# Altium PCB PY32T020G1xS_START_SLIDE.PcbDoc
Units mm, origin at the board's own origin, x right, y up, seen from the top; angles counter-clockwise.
Board outline 105.31 x 81.08 mm, 2 copper layers (Top Layer, Bottom Layer); 86 components, 86 nets, 275 pads, 131 vias.
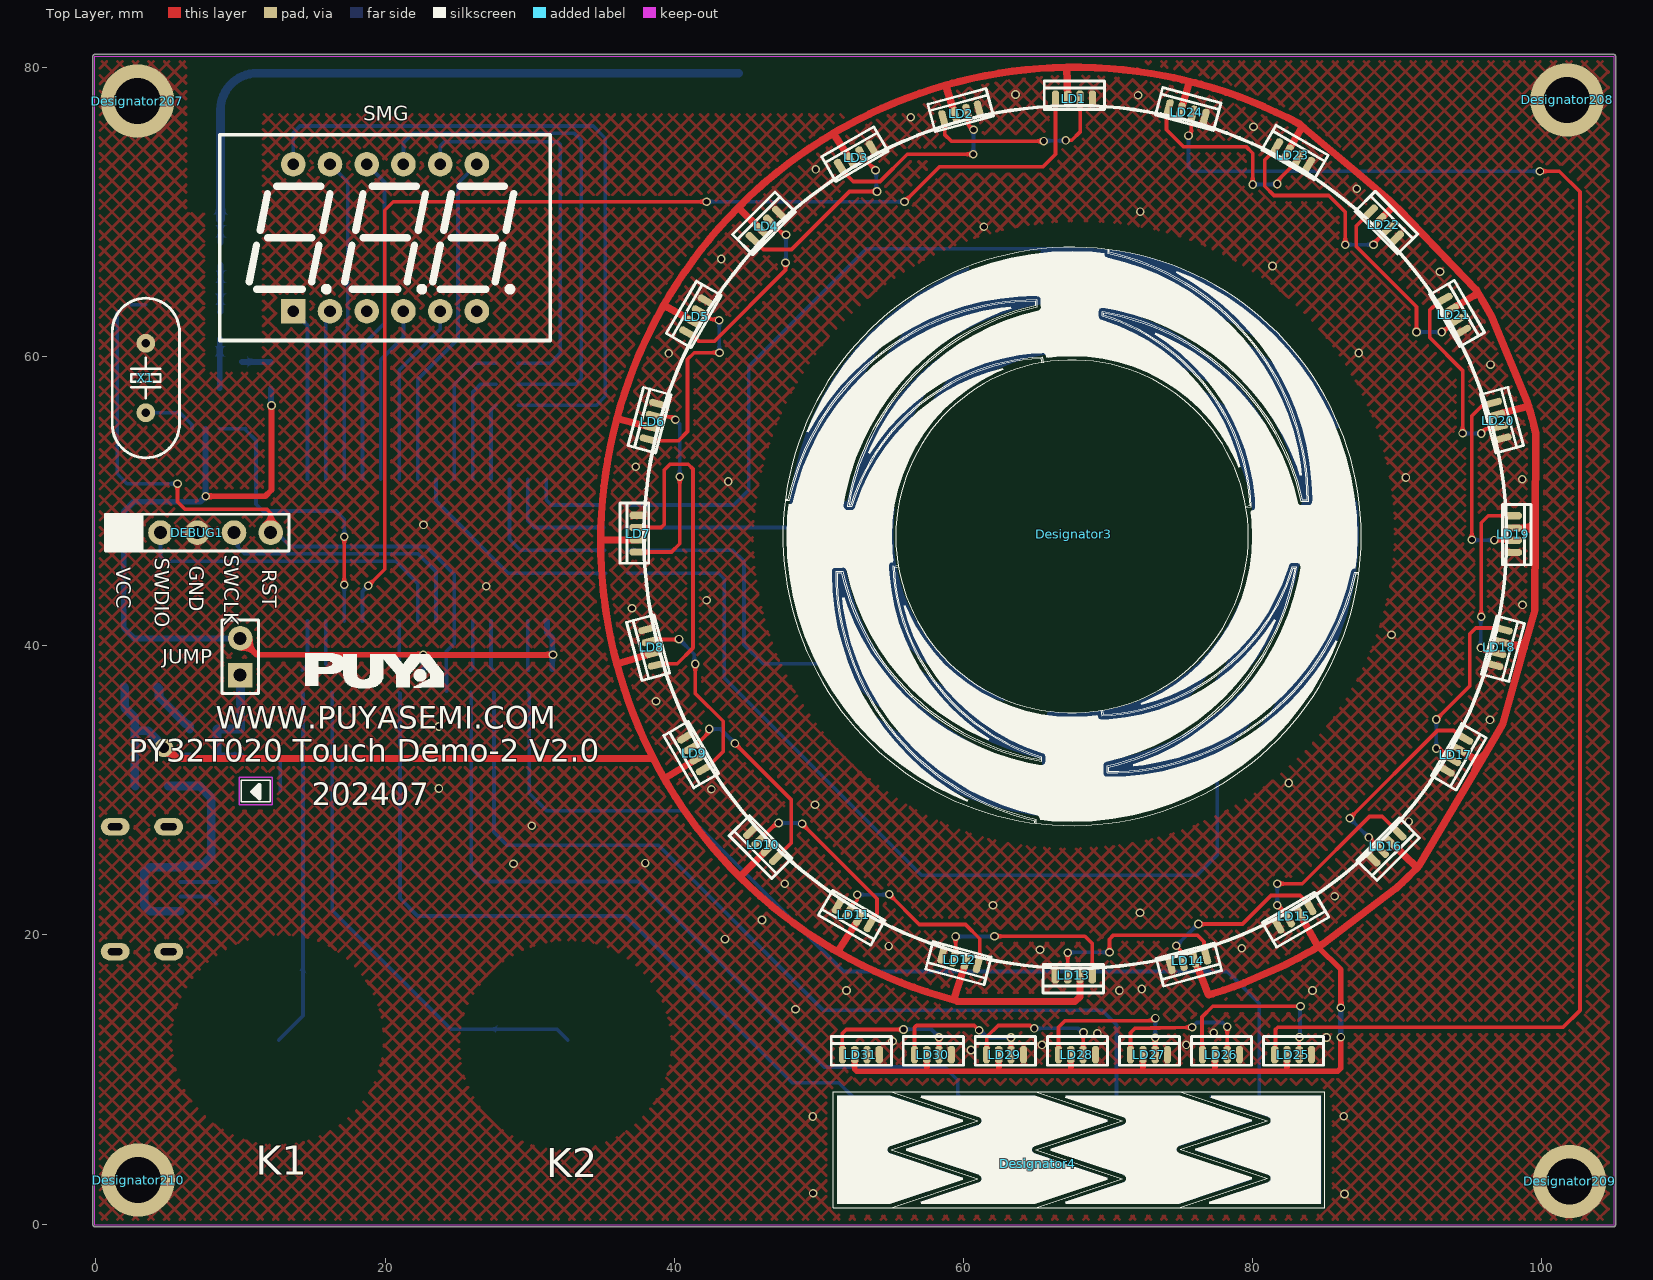
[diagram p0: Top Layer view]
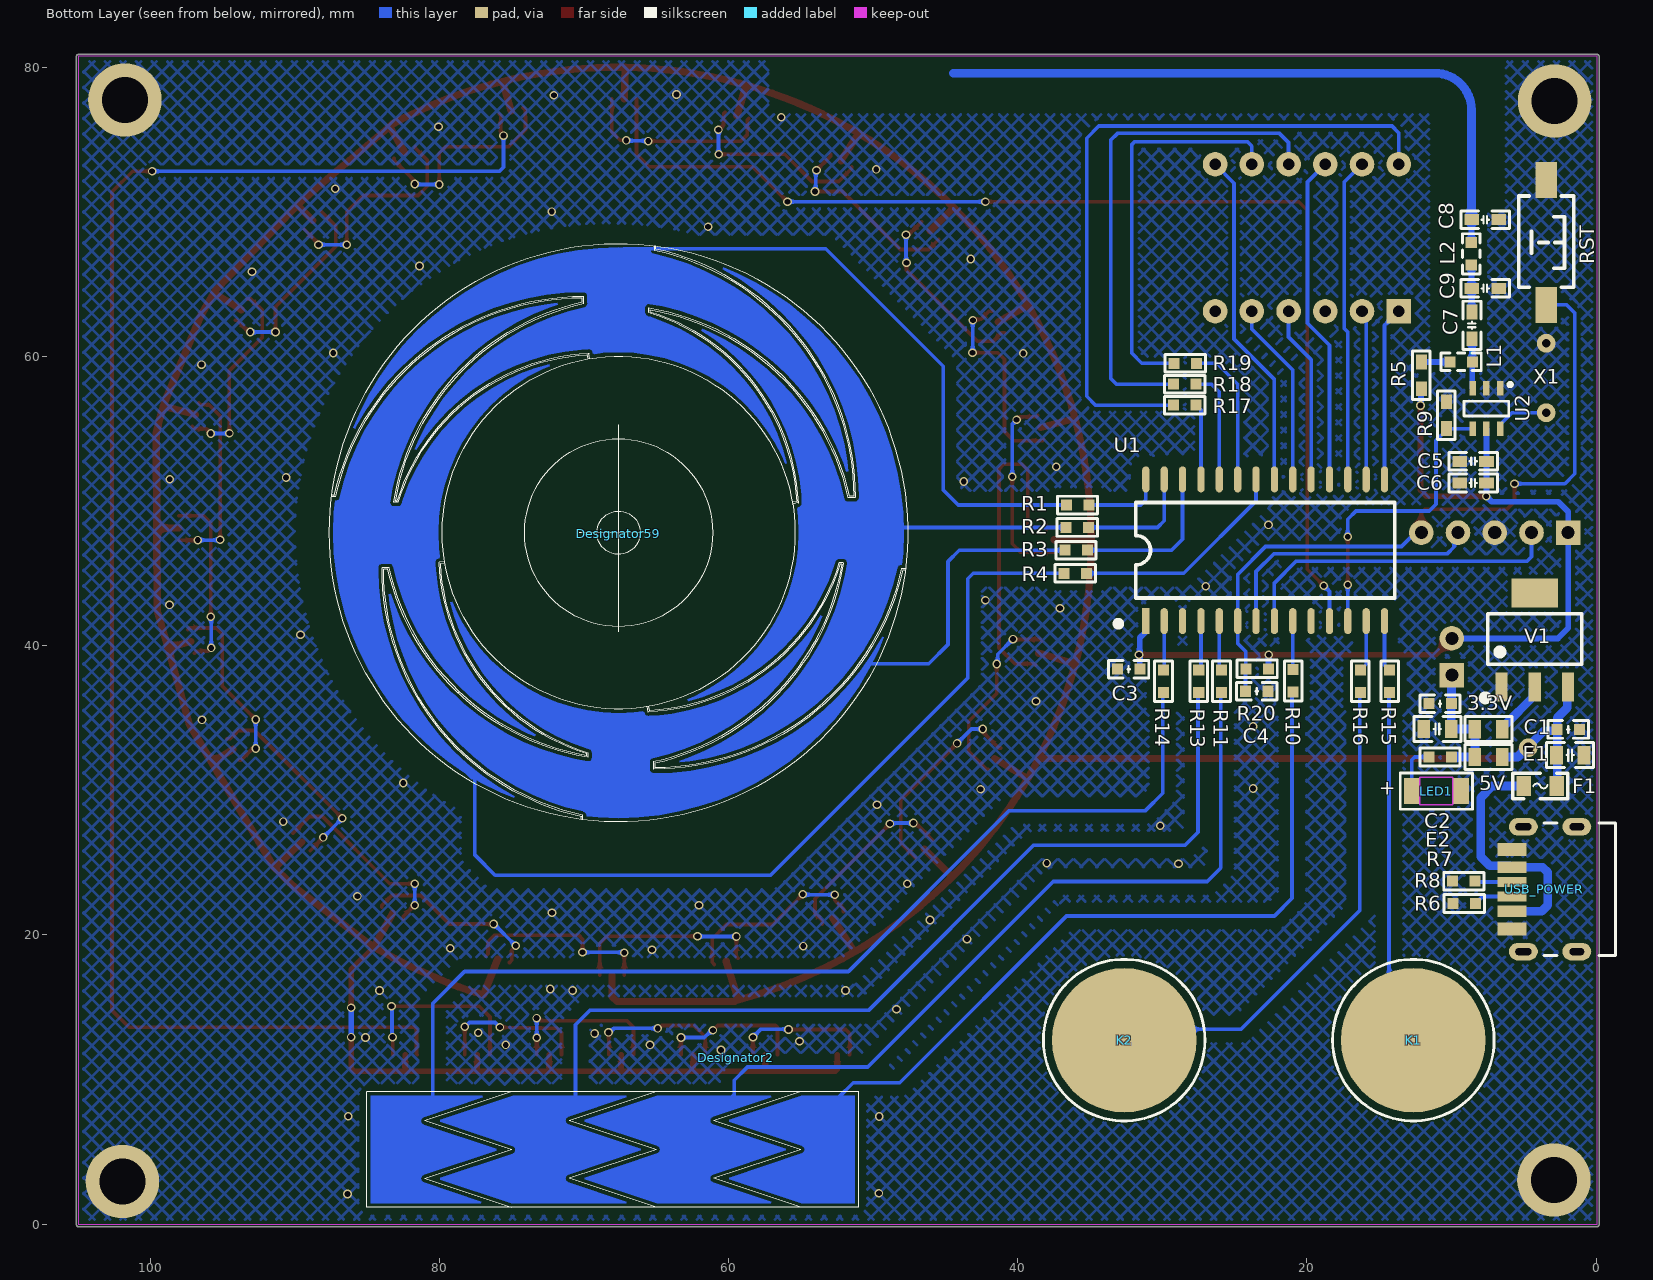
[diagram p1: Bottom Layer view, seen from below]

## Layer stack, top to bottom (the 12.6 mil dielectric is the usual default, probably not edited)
Top Solder: solder mask 0.0102, Solder Resist, Dk 3.5
Top Layer: signal copper 0.0356
Dielectric 1: dielectric 0.32, FR-4, Dk 4.8
Bottom Layer: signal copper 0.0356
Bottom Solder: solder mask 0.0102, Solder Resist, Dk 3.5

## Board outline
-0.076,-0.178 cw(c-0.076,-0.051) -0.204,-0.051 -0.204,80.772 cw(c-0.076,80.772) -0.076,80.899 104.978,80.899 cw(c104.978,80.772) 105.106,80.772 105.106,-0.051 cw(c104.978,-0.051) 104.978,-0.178

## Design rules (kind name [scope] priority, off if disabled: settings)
Clearance TK [InNet('TK1')] p1: gap=0.768 ignorepadtopadclearanceinfootprint=FALSE
Clearance NetR_10 [InNet('NetR16_2')] p2: gap=0.768 ignorepadtopadclearanceinfootprint=FALSE
Clearance NetR_9 [InNet('NetR15_2')] p3: gap=0.768 ignorepadtopadclearanceinfootprint=FALSE
Clearance NetR_8 [InNet('NetR14_2')] p4: gap=0.768 ignorepadtopadclearanceinfootprint=FALSE
Clearance NetR_7 [InNet('NetR13_2')] p5: gap=0.768 ignorepadtopadclearanceinfootprint=FALSE
Clearance NetR_6 [InNet('NetR11_2')] p6: gap=0.768 ignorepadtopadclearanceinfootprint=FALSE
Clearance NetR_5 [InNet('NetR10_2')] p7: gap=0.768 ignorepadtopadclearanceinfootprint=FALSE
Clearance NetR_4 [InNet('NetR4_2')] p8: gap=0.768 ignorepadtopadclearanceinfootprint=FALSE
Clearance NetR_3 [InNet('NetR3_2')] p9: gap=0.768 ignorepadtopadclearanceinfootprint=FALSE
Clearance NetR_2 [InNet('NetR2_2')] p10: gap=0.768 ignorepadtopadclearanceinfootprint=FALSE
Clearance NetR_1 [InNet('NetR1_2')] p11: gap=0.768 ignorepadtopadclearanceinfootprint=FALSE
Clearance TK_10 [InNet('TK10')] p12: gap=0.768 ignorepadtopadclearanceinfootprint=FALSE
Clearance TK_9 [InNet('TK9')] p13: gap=0.768 ignorepadtopadclearanceinfootprint=FALSE
Clearance TK_8 [InNet('TK8')] p14: gap=0.768 ignorepadtopadclearanceinfootprint=FALSE
Clearance TK_7 [InNet('TK7')] p15: gap=0.768 ignorepadtopadclearanceinfootprint=FALSE
Clearance TK_6 [InNet('TK6')] p16: gap=0.768 ignorepadtopadclearanceinfootprint=FALSE
Clearance TK_5 [InNet('TK5')] p17: gap=0.768 ignorepadtopadclearanceinfootprint=FALSE
Clearance TK_4 [InNet('TK4')] p18: gap=0.768 ignorepadtopadclearanceinfootprint=FALSE
Clearance TK_3 [InNet('TK3')] p19: gap=0.768 ignorepadtopadclearanceinfootprint=FALSE
Clearance TK_2 [InNet('TK2')] p20: gap=0.768 ignorepadtopadclearanceinfootprint=FALSE
Clearance TK_1 [InNet('TK1')] p21: gap=0.768 ignorepadtopadclearanceinfootprint=FALSE
Clearance [All] p22: gap=0.254 ignorepadtopadclearanceinfootprint=FALSE except(0: Arc-Hole Track-Hole SMDPad-Hole THPad-Hole Via-Hole Fill-Hole Poly-Hole Region-Hole Text-Hole)
PlaneConnect PlaneConnect_1 [InNet('GND')] p1: planeconnectstyle=Direct reliefexpansion=0.508 reliefentries=4 reliefconductorwidth=0.254 reliefairgap=0.254
PlaneConnect [All] p2: planeconnectstyle=Relief reliefexpansion=0.508 reliefentries=4 reliefconductorwidth=0.254 reliefairgap=0.254
PolygonConnect PolygonConnect_1 [InNet('GND')] p1: connectstyle=Direct reliefconductorwidth=0.254 reliefentries=4 polygonreliefangle="90 Angle" airgapwidth=0.254
PolygonConnect [All] p2: connectstyle=Relief reliefconductorwidth=0.254 reliefentries=4 polygonreliefangle="90 Angle" airgapwidth=0.254
RoutingVias [All] p1: holewidth=0.711 width=1.27 viastyle="Through Hole" minholewidth=0.711 minwidth=1.27 maxholewidth=0.711 maxwidth=1.27
SolderMaskExpansion [All] p1: expansion=0.102 istentingtop=FALSE
Width [All] p1: maxlimit=0.8 minlimit=0.254 preferedwidth=0.254
29 further rules are at their usual default settings.

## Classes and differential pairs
component class PY32T020_BOARD5_V1.0: C1 C2 C3 C4 DEBUG1 E1 E2 F1 LD1 LD2 LD3 LD4 LD5 LD6 LD7 LD8 LD9 LD10 LD11 LD12 LD13 LD14 LD15 LD16 LD17 LD18 LD19 LD20 LD21 LD22 LD23 LD24 LD25 LD26 LD27 LD28 LD29 LD30 LD31 R1 R2 R3 R4 R6 R7 R8 R10 R11 R13 R14 R15 R16 R17 R18 R19 R20 RST SMG U1 USB_POWER V1

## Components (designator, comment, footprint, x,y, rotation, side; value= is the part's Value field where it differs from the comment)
3.3V "NC" "R 0805_L" 7.442,34.239 r180 bottom (schematic designator R7)
5V "0R" "R 0805_L" 7.442,32.309 r0 bottom (schematic designator R7)
C1 "104" "C 0603_L" 1.93,34.214 r0 bottom
C2 "104" "C 0603_L" 10.795,35.992 r180 bottom
C3 "104" "C 0603_L" 32.334,38.379 r180 bottom
C4 "104" "C 0603_L" 23.47,36.855 r0 bottom
C5 "100NF" "C 0603_M" 8.509,52.756 r180 bottom
C6 "1UF" "C 0603_M" 8.509,51.257 r180 bottom
C7 "10PF" "C 0603_M" 8.585,62.154 r90 bottom
C8 "1.5PF" "C 0603_M" 7.671,69.469 r0 bottom
C9 "NC" "C 0603_M" 7.671,64.719 r0 bottom
DEBUG1 "ISP" ISP_DIP_2.54_5P 1.93,47.828 r0 top
Designator2 "Comment" wheel 59.5,11.5 r0 bottom
Designator3 "Comment" "circular ring_top" 67.64,47.727 r0 top
Designator4 "Comment" WHEEL_TOP 65.151,4.191 r0 top
Designator59 "Comment" PAD_Wheel 67.64,47.752 r90 bottom
Designator207 "Comment" "M3 125X200" 7.314,74.711 r0 top
Designator208 "Comment" "M3 125X200" 106.196,74.787 r0 top
Designator209 "Comment" "M3 125X200" 106.374,-0.014 r0 top
Designator210 "Comment" "M3 125X200" 7.364,0.087 r0 top
E1 "10uF/10V" "C 0805_L" 1.793,32.436 r180 bottom
E2 "10uF/10V" "C 0805_L" 10.973,34.239 r0 bottom
F1 "500ma" "FU 0805" 3.861,30.302 r180 bottom
JUMP "Comment" HDR2.54-LI-2P 9.982,39.243 r90 top
K1 "Comment" Touch 12.64,12.727 r180 bottom
K2 "Comment" Touch 32.64,12.727 r180 bottom
L1 "100NH" "L 0603_L" 9.337,59.639 r0 bottom
L2 "18NH" "L 0603_L" 8.636,67.107 r270 bottom
LD1 "LED1" LED4020 67.64,78.283 r0 top
LD2 "LED1" LED4020 59.715,77.241 r15 top
LD3 "LED1" LED4020 52.349,74.168 r30 top
LD4 "LED1" LED4020 46.025,69.342 r45 top
LD5 "LED1" LED4020 41.148,62.992 r60 top
LD6 "LED1" LED4020 38.075,55.626 r75 top
LD7 "LED1" LED4020 37.033,47.752 r90 top
LD8 "LED1" LED4020 37.998,39.776 r105 top
LD9 "LED1" LED4020 40.999,32.33 r120 top
LD10 "LED1" LED4020 45.847,25.908 r135 top
LD11 "LED1" LED4020 52.197,20.98 r150 top
LD12 "LED1" LED4020 59.639,17.831 r165 top
LD13 "LED1" LED4020 67.64,16.764 r180 top
LD14 "LED1" LED4020 75.692,17.755 r195 top
LD15 "LED1" LED4020 83.113,20.882 r210 top
LD16 "LED1" LED4020 89.56,25.806 r225 top
LD17 "LED1" LED4020 94.472,32.245 r240 top
LD18 "LED1" LED4020 97.525,39.769 r255 top
LD19 "LED1" LED4020 98.493,47.726 r270 top
LD20 "LED1" LED4020 97.434,55.702 r285 top
LD21 "LED1" LED4020 94.31,63.119 r300 top
LD22 "LED1" LED4020 89.383,69.444 r315 top
LD23 "LED1" LED4020 83.007,74.32 r330 top
LD24 "LED1" LED4020 75.565,77.343 r345 top
LD25 "LED1" LED4020 82.797,12.19 r0 top
LD26 "LED1" LED4020 77.814,12.19 r0 top
LD27 "LED1" LED4020 72.832,12.19 r0 top
LD28 "LED1" LED4020 67.85,12.19 r0 top
LD29 "LED1" LED4020 62.867,12.19 r0 top
LD30 "LED1" LED4020 57.885,12.19 r0 top
LD31 "LED1" LED4020 52.903,12.19 r0 top
LED1 "Comment" T-LED 11.151,29.921 r0 top
R1 "4.3K" "R 0603_L" 35.865,49.733 r0 bottom
R2 "4.3K" "R 0603_L" 35.89,48.184 r0 bottom
R3 "4.3K" "R 0603_L" 35.966,46.609 r0 bottom
R4 "4.3K" "R 0603_L" 36.017,45.009 r0 bottom
R5 "0R" "R 0603_M" 12.09,58.699 r90 bottom
R6 "5.1K" "R 0603_L" 9.119,22.174 r180 bottom
R7 "1K" "R 0603_L" 10.795,32.309 r180 bottom
R8 "5.1K" "R 0603_L" 9.144,23.724 r180 bottom
R9 "100K" "R 0603_M" 10.363,55.956 r90 bottom
R10 "4.3K" "R 0603_L" 20.955,37.567 r270 bottom
R11 "4.3K" "R 0603_L" 25.908,37.541 r270 bottom
R13 "4.3K" "R 0603_L" 27.483,37.541 r270 bottom
R14 "4.3K" "R 0603_L" 29.921,37.541 r270 bottom
R15 "4.3K" "R 0603_L" 14.275,37.541 r270 bottom
R16 "4.3K" "R 0603_L" 16.307,37.541 r270 bottom
R17 "100R" "R 0603_L" 28.448,56.642 r180 bottom
R18 "100R" "R 0603_L" 28.448,58.09 r180 bottom
R19 "100R" "R 0603_L" 28.423,59.538 r180 bottom
R20 "10K" "R 0603_L" 23.444,38.405 r180 bottom
RST "6x6x5" "TSW SMD-3*6*5" 3.454,67.894 r270 bottom (schematic designator RST1)
SMG "3631A" "SMG 0.36-3P" 20,68.224 r0 top (schematic designator SMG1)
U1 "PY32T020G16" SOP28_L 22.885,46.609 r90 bottom
U2 "F4455B" SOT23-6L 7.595,56.413 r0 bottom
USB_POWER "USB-C" USB-C/S_C -1.219,23.165 r90 bottom (schematic designator USB_POWER1)
V1 "AMS1117-3V3" SOT223_N 4.242,40.462 r180 bottom
X1 "6.7458MHZ" "OSC HC-49S" 3.454,58.522 r90 top

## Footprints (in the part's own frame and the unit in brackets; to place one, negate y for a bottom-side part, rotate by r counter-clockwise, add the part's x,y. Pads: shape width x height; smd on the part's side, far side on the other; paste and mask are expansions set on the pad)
"C 0603_L" [mil] "无极性贴片电容"
  rect 30x30 smd: 1(-30.59,0) 2(30.59,0)
  silkscreen extent -55,-24 55,24, body extent -31,-16 31,16, height 32
"C 0603_M" [mil] "无极性贴片电容"
  rect 40x30 smd: 1(-36.5,0) 2(36.5,0)
  silkscreen extent -66,-24 66,24, body extent -31,-16 31,16, height 32
"C 0805_L" [mil] "无极性贴片电容"
  rect 35x50 smd: 1(-37.41,0) 2(37.4,0)
  silkscreen extent -64,-34 64,34, body extent -39,-24 39,24, height 20
"circular ring_top" [mm]
  silkscreen extent -20.12,-20.16 19.87,19.84
"FU 0805" [mil] "贴片保险丝"
  rect 40x55 smd: 1(-45,0) 2(45,0)
  silkscreen extent -75,-35 75,35, body extent -39,-24 39,24, height 20
HDR2.54-LI-2P [mm] "排针，2脚"
  rect 1.7x1.7 hole 0.9: 1(-1.27,0)
  round 1.7 hole 0.9: 2(1.27,0)
  silkscreen extent -2.54,-1.27 2.54,1.27, body extent -2.54,-1.27 2.54,1.27, height 8.5
ISP_DIP_2.54_5P [mm] "5P 下载端口"
  rect 1.7x1.7 hole 0.9: 1(0,0)
  round 1.7 hole 0.9: 2(2.54,0) 3(5.08,0) 4(7.62,0) 5(10.16,0)
  silkscreen extent -1.27,-1.27 11.43,1.27
"L 0603_L" [mil] "小功率贴片电感"
  rect 30x30 smd: 1(-30.59,0) 2(30.59,0)
  silkscreen extent -55,-24 55,24, body extent -31,-16 31,16, height 31
LED4020 [mm]
  oct 0.5x1.2 smd: 1(-1.27,-0.466) 2(-0.42,-0.466) 3(0.43,-0.466) 4(1.28,-0.466)
  silkscreen extent -2.05,-1.2 2.13,0.77
"M3 125X200" [mm] "M3螺丝孔，孔125Mil，焊盘200Mil"
  round 5.08 hole 3.175: 1(-4.444,2.962)
"OSC HC-49S" [mm]
  round 1.3 hole 0.6: 1(-2.4,0) 2(2.4,0)
  silkscreen extent -5.52,-2.32 5.52,2.33, body extent -5.53,-2.32 5.53,2.32, height 4.13
PAD_Wheel [mm]
  Top Layer region: 178 vertices and 0 holes, not listed, extent 4.285,-15.918 19.803,18.314
  Top Layer region: 178 vertices and 0 holes, not listed, extent -15.818,-19.764 18.414,-4.247
  Top Layer region: 178 vertices and 0 holes, not listed, extent -18.275,4.184 15.957,19.702
  Top Layer region: 181 vertices and 0 holes, not listed, extent -19.664,-18.376 -4.146,15.856
  silkscreen extent -19.93,-20.03 20.07,19.97
"R 0603_L" [mil] "1/10W贴片电阻"
  rect 30x30 smd: 1(-30.59,0) 2(30.59,0)
  silkscreen extent -55,-24 55,24, body extent -31,-16 31,16, height 16
"R 0603_M" [mil] "1/10W贴片电阻"
  rect 40x30 smd: 1(-36.5,0) 2(36.5,0)
  silkscreen extent -66,-24 66,24, body extent -31,-16 31,16, height 16
"R 0805_L" [mil] "1/8W贴片电阻"
  rect 35x50 smd: 1(-37.41,0) 2(37.4,0)
  silkscreen extent -64,-34 64,34, body extent -39,-25 39,25, height 20
"SMG 0.36-3P" [mm] "22.5*14*7.2mm(长宽厚)"
  rect 1.7x1.7 hole 0.8: 1(-6.35,-5.08)
  round 1.7 hole 0.8: 2(-3.81,-5.08) 3(-1.27,-5.08) 4(1.27,-5.08) 5(3.81,-5.08) 6(6.35,-5.08) 7(6.35,5.08) 8(3.81,5.08) 9(1.27,5.08) 10(-1.27,5.08) 11(-3.81,5.08) 12(-6.35,5.08)
  silkscreen extent -11.43,-7.11 11.43,7.11, body extent -11.25,-7 11.25,7, height 7.2
SOP28_L [mm] "17.9*10.6*2.6mm（长宽高）"
  rect 1.8x0.5 smd: 1(-4.9,8.255)
  oval 1.8x0.5 smd: 2(-4.9,6.985) 3(-4.9,5.715) 4(-4.9,4.445) 5(-4.9,3.175) 6(-4.9,1.905) 7(-4.9,0.635) 8(-4.9,-0.635) 9(-4.9,-1.905) 10(-4.9,-3.175) 11(-4.9,-4.445) 12(-4.9,-5.715) 13(-4.9,-6.985) 14(-4.9,-8.255) 15(4.9,-8.255) 16(4.9,-6.985) 17(4.9,-5.715) 18(4.9,-4.445) 19(4.9,-3.175) 20(4.9,-1.905) 21(4.9,-0.635) 22(4.9,0.635) 23(4.9,1.905) 24(4.9,3.175) 25(4.9,4.445) 26(4.9,5.715) 27(4.9,6.985) 28(4.9,8.255)
  silkscreen extent -5.23,-8.95 3.3,10.31, body extent -5.15,-8.95 5.15,8.95, height 2.7
SOT23-6L [mm] "3x1.6x1.1mm(长宽高)"
  rect 0.45x1 smd: 1(-0.95,-1.397) 2(0,-1.397) 3(0.95,-1.397) 4(0.95,1.397) 5(0,1.397) 6(-0.95,1.397)
  silkscreen extent -1.77,-1.78 1.55,0.51, body extent -1.5,-1.4 1.5,1.4, height 1.15
SOT223_N [mm] "6.4x7x1.6mm(长宽高)"
  rect 0.85x2 smd: 1(-2.3,-3.302) 2(0,-3.302) 3(2.3,-3.302)
  rect 3.2x2 smd: 2(0,3.175)
  silkscreen extent -3.63,-4.26 3.25,1.75, body extent -3.25,-3.51 3.25,3.51, height 1.65
T-LED [mm]
  rect 1.1x1.8 smd far side: 1(1.598,0.025) 2(-1.802,0.025)
  Keep-Out Layer lines w0.1: -1.252,-0.925 1.048,-0.925 1.048,0.975 -1.252,0.975 -1.252,-0.925
  silkscreen extent -1.1,-0.73 0.9,0.77
Touch [mm]
  round 10 smd paste-10: Touch(0,0)
  silkscreen extent -5.59,-5.59 5.59,5.59
"TSW SMD-3*6*5" [mm] "3*6*5mm"
  rect 2.5x1.5 smd: 1(-4.318,0) 2(4.318,0)
  silkscreen extent -3.21,-1.9 3.09,1.9, body extent -4.6,-1.75 4.6,1.75, height 5.1
USB-C/S_C [mm] "Type-C 6P母座"
  oval 1.2x2 hole 0.5 slot 1 at 90 deg: 0(-4.32,2.55) 0(4.32,2.55)
  oval 1.2x2 hole 0.5 slot 1.1 at 90 deg: 0(-4.32,6.25) 0(4.32,6.25)
  rect 0.7x2 smd: A5(-0.5,7.05) B5(0.5,7.05)
  rect 0.8x2 smd: A9(1.52,7.05) B9(-1.52,7.05)
  rect 0.9x2 smd: A12(2.75,7.05) B12(-2.75,7.05)
  silkscreen extent -4.57,-0.13 4.57,4.83, body extent -4.47,0 4.48,7.05, height 3.16
wheel [mm]
  Top Layer region: 0.46,8.405 0.46,8.278 -4.576,6.6 -4.592,6.59 -4.611,6.585 -4.638,6.564 -4.668,6.547 -4.68,6.532 -4.695,6.52 -4.712,6.491 -4.733,6.464 -4.738,6.445 -4.748,6.428 -4.752,6.394 -4.761,6.361 -4.758,6.342 -4.761,6.323 -4.752,6.29 -4.748,6.256 -4.738,6.239 -4.733,6.22 -4.712,6.193 -4.695,6.164 -4.68,6.152 -4.668,6.137 -4.638,6.12 -4.611,6.099 -4.592,6.094 -4.576,6.084 0.46,4.405 0.46,4.278 -4.534,2.614 -8.218,2.614 -8.218,10.07 -4.532,10.07
  Top Layer region: 10.46,8.405 10.46,8.278 5.424,6.6 5.408,6.59 5.389,6.585 5.362,6.564 5.332,6.547 5.32,6.532 5.305,6.52 5.288,6.491 5.267,6.464 5.262,6.445 5.252,6.428 5.248,6.394 5.239,6.361 5.242,6.342 5.239,6.323 5.248,6.29 5.252,6.256 5.262,6.239 5.267,6.22 5.288,6.193 5.305,6.164 5.32,6.152 5.332,6.137 5.362,6.12 5.389,6.099 5.408,6.094 5.424,6.084 10.46,4.405 10.46,4.278 5.466,2.614 -2.417,2.614 -2.438,2.739 1.596,4.084 1.613,4.094 1.632,4.099 1.659,4.12 1.689,4.137 1.701,4.152 1.716,4.164 1.733,4.193 1.754,4.22 1.759,4.239 1.768,4.256 1.773,4.29 1.782,4.323 1.779,4.342 1.782,4.361 1.773,4.394 1.768,4.428 1.759,4.445 1.754,4.464 1.733,4.491 1.716,4.52 1.701,4.532 1.689,4.547 1.659,4.564 1.632,4.585 1.613,4.59 1.596,4.6 -3.439,6.278 -3.439,6.405 1.596,8.084 1.613,8.094 1.632,8.099 1.659,8.12 1.689,8.137 1.701,8.152 1.716,8.164 1.733,8.193 1.754,8.22 1.759,8.239 1.768,8.256 1.773,8.29 1.782,8.323 1.779,8.342 1.782,8.361 1.773,8.394 1.768,8.428 1.759,8.445 1.754,8.464 1.733,8.491 1.716,8.52 1.701,8.532 1.689,8.547 1.659,8.564 1.632,8.585 1.613,8.59 1.596,8.6 -2.436,9.944 -2.416,10.07 5.468,10.07
  Top Layer region: 20.46,8.423 20.46,8.296 15.424,6.617 15.408,6.608 15.389,6.603 15.362,6.582 15.332,6.565 15.32,6.55 15.305,6.538 15.288,6.508 15.267,6.481 15.262,6.462 15.252,6.445 15.248,6.412 15.239,6.379 15.242,6.36 15.239,6.34 15.248,6.307 15.252,6.274 15.262,6.257 15.267,6.238 15.288,6.211 15.305,6.181 15.32,6.169 15.332,6.154 15.362,6.137 15.389,6.116 15.408,6.111 15.424,6.102 20.46,4.423 20.46,4.296 15.424,2.617 15.418,2.614 7.583,2.614 7.562,2.739 11.596,4.084 11.613,4.094 11.632,4.099 11.659,4.12 11.689,4.137 11.701,4.152 11.716,4.164 11.733,4.193 11.754,4.22 11.759,4.239 11.768,4.256 11.773,4.29 11.782,4.323 11.779,4.342 11.782,4.361 11.773,4.394 11.768,4.428 11.759,4.445 11.754,4.464 11.733,4.491 11.716,4.52 11.701,4.532 11.689,4.547 11.659,4.564 11.632,4.585 11.613,4.59 11.596,4.6 6.561,6.278 6.561,6.405 11.596,8.084 11.613,8.094 11.632,8.099 11.659,8.12 11.689,8.137 11.701,8.152 11.716,8.164 11.733,8.193 11.754,8.22 11.759,8.239 11.768,8.256 11.773,8.29 11.782,8.323 11.779,8.342 11.782,8.361 11.773,8.394 11.768,8.428 11.759,8.445 11.754,8.464 11.733,8.491 11.716,8.52 11.701,8.532 11.689,8.547 11.659,8.564 11.632,8.585 11.613,8.59 11.596,8.6 7.564,9.944 7.584,10.07 15.52,10.07
  Top Layer region: 25.238,2.614 17.53,2.614 17.51,2.739 21.596,4.102 21.613,4.111 21.632,4.116 21.659,4.137 21.689,4.154 21.701,4.169 21.716,4.181 21.733,4.211 21.754,4.238 21.759,4.257 21.768,4.274 21.773,4.307 21.782,4.34 21.779,4.359 21.782,4.379 21.773,4.412 21.768,4.445 21.759,4.462 21.754,4.481 21.733,4.508 21.716,4.538 21.701,4.55 21.689,4.565 21.659,4.582 21.632,4.603 21.613,4.608 21.596,4.617 16.561,6.296 16.561,6.423 21.596,8.102 21.613,8.111 21.632,8.116 21.659,8.137 21.689,8.154 21.701,8.169 21.716,8.181 21.733,8.211 21.754,8.238 21.759,8.257 21.768,8.274 21.773,8.307 21.782,8.34 21.779,8.359 21.782,8.379 21.773,8.412 21.768,8.445 21.759,8.462 21.754,8.481 21.733,8.508 21.716,8.538 21.701,8.55 21.689,8.565 21.659,8.582 21.632,8.603 21.613,8.608 21.596,8.617 17.616,9.944 17.637,10.07 25.238,10.07
  silkscreen extent -8.49,2.34 25.51,10.36
WHEEL_TOP [mm]
  silkscreen extent -14.15,-3.05 19.85,4.97

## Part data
3.3V 5V R1 R2 R3 R4 R5 R7 R9 R10 R11 R13 R14 R15 R16 R17 R18 R19 R20: library part R, "贴片电阻"
C1 C2 C3 C4 C5 C6 C7 C8 C9: library part C, "无极性贴片电容"
DEBUG1: library part ISP_5Pin, "程序下载端口"
E1 E2: library part C-CM, "贴片电解电容"
F1: library part FU, "贴片保险丝"
L1 L2: library part L, "小功率贴片电感"
LD1 LD2 LD3 LD4 LD5 LD6 LD7 LD8 LD9 LD10 LD11 LD12 LD13 LD14 LD15 LD16 LD17 LD18 LD19 LD20 LD21 LD22 LD23 LD24 LD25 LD26 LD27 LD28 LD29 LD30 LD31: library part LED4020
R6 R8: library part R
RST: library part "TSW DIP-2Pin-6x6", "2脚直插6x6轻触开关"
SMG: "0.36寸3位共阴数码管"
USB_POWER: library part USB-C_6P/S, "USB-C_6P型母接口"
V1: library part AMS1117, "三端稳压芯片"
X1: library part XTAL-2P, "2脚无源脚晶振"

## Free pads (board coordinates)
  round 12 on Top Overlay: 8(12.294,12.7) 8(32.487,12.522)

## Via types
v1: diameter 0.6, hole 0.4, Top Layer to Bottom Layer, 130 vias
v2: diameter 1.27, hole 0.711, Top Layer to Bottom Layer, 1 vias

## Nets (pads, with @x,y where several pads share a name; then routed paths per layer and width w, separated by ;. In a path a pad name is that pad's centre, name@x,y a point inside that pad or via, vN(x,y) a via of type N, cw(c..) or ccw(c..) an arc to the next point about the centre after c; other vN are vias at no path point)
BEEP: 
COM0: R17.2 U1.25 | length 5.3
  Bottom Layer w0.254: U1.25 27.33,56.301 R17.2
COM1: R18.2 U1.24 | length 7.9
  Bottom Layer w0.254: U1.24 26.06,57.556 26.594,58.09 R18.2
COM2: R19.2 U1.23 | length 10
  Bottom Layer w0.254: U1.23 24.79,58.09 26.238,59.538 R19.2
GND: C1.1 C2.1 C3.1 C4.1 C5.1 C6.1 C8.1 C9.1 DEBUG1.3 Designator207.1 Designator208.1 Designator209.1 Designator210.1 E1.2 E2.2 LD1.4 LD2.4 LD3.4 LD4.4 LD5.4 LD6.4 LD7.4 LD8.4 LD9.4 LD10.4 LD11.4 LD12.4 LD13.4 LD14.4 LD15.4 LD16.4 LD17.4 LD18.4 LD19.4 LD20.4 LD21.4 LD22.4 LD23.4 LD24.4 LD25.4 LD26.4 LD27.4 LD28.4 LD29.4 LD30.4 LD31.4 LED1.2 R6.1 R8.1 R9.2 RST.1 U1.3 U2.1 U2.2 USB_POWER.A12 USB_POWER.B12 V1.1 X1.2
  other v1: 86.36,2.083 49.606,2.134 49.581,7.442 86.309,7.468 60.528,12.04 65.43,12.395 75.413,12.395 55.093,12.649 85.115,12.903 69.266,13.183 77.318,13.233 48.387,14.859 51.918,16.154 70.79,16.154 84.15,16.154 72.339,16.256 65.303,18.974 79.248,19.075 54.839,19.228 43.51,19.71 46.076,21.031 72.212,21.539 62.052,22.047 85.674,22.682 47.65,23.546 28.88,24.917 37.998,24.968 30.143,27.552 90.805,27.838 49.733,29.007 42.57,30.074 23.724,30.124 82.499,30.505 23.724,34.417 96.418,34.874 38.735,36.17 89.611,40.767 37.084,42.596 98.671,42.827 42.24,43.155 27,44.12 22.657,48.362 43.739,51.359 98.654,51.511 90.602,51.638 37.338,52.375 96.459,59.445 39.624,60.223 87.351,60.249 92.964,65.862 81.382,66.269 43.256,66.751 61.417,68.986 72.238,70.028 87.198,71.603 49.784,72.949 80.061,75.895 56.363,76.556 72.085,78.08 63.602,78.13
LED_D: LD1.1 U1.11 | length 80.8
  Top Layer w0.254: v1(18.836,44.158) 19.977,45.299 19.977,70.117 20.574,70.714 v1(42.24,70.714) ; v1(55.931,70.714) 58.344,73.127 65.507,73.127 66.37,73.99 LD1.1
  Bottom Layer w0.254: U1.11 18.44,43.764 v1@18.821,44.145 ; v1(42.24,70.714) v1(55.931,70.714)
Net1_1: 3.3V.2 V1.2@4.242,37.16 | length 3.9
  Bottom Layer w0.6: V1.2@4.242,37.16 4.367,37.035 4.367,36.46 6.253,34.574 6.348,34.574 6.492,34.43 3.3V.2
Net1_2: 3.3V.1 5V.2 C2.2 E2.1 JUMP.1 R7.2 | length 8.9
  Bottom Layer w0.6: 5V.2@8.379,32.322 8.379,34.226 3.3V.1 E2.1 10.02,34.242 C2.2@10.02,35.992 ; 5V.2 R7.2 ; JUMP.1 10,37.955 10,36.01 C2.2
NetBEEP1_2: 
NetC7_1: C7.1 L1.1 U2.3 | length 3.4
  Bottom Layer w0.4: U2.3 8.565,57.831 8.565,61.206 C7.1
NetC7_2: C7.2 C9.2 L2.2 | length 3.3
  Bottom Layer w0.4: C7.2 8.611,63.106 8.611,66.304 L2.2
NetC8_2: C8.2 L2.1 | length 50.5
  Bottom Layer w0.4: C8.2 8.617,69.45 8.617,67.903 L2.1
  Bottom Layer w0.6: C8.2 8.623,69.494 8.623,77.076 ; 44.45,79.604 11.151,79.604 ; 8.623,77.076 cw(c11.151,77.076) 11.151,79.604 ; 8.623,77.076 cw(c11.151,77.076) 11.151,79.604
NetL1_2: L1.2 R5.2 | length 2
  Bottom Layer w0.4: L1.2 10.12,59.633 12.084,59.633 R5.2
NetLD1_3: LD1.3 LD2.1 | length 13.2
  Top Layer w0.254: LD2.1 58.7,76.372 58.7,75.361 59.157,74.905 v1(65.557,74.905) ; v1(67.081,74.955) 67.488,74.955 68.07,75.538 LD1.3
  Bottom Layer w0.254: v1(65.557,74.905) 65.583,74.93 67.056,74.93 v1(67.081,74.955)
NetLD2_3: LD2.3 LD3.1 | length 13.6
  Top Layer w0.254: LD3.1 51.483,73.002 52.374,72.111 54.229,72.111 56.109,73.99 v1(60.681,73.99) ; LD2.3 60.342,76.812 60.342,76.001 60.651,75.692 v1(60.706,75.692)
  Bottom Layer w0.254: v1(60.681,73.99) 60.693,74.003 60.693,75.679 v1(60.706,75.692)
NetLD3_3: LD3.3 LD4.1 | length 13.5
  Top Layer w0.254: LD4.1 46.16,67.412 48.108,67.412 52.121,71.425 v1(54.026,71.425) ; LD3.3 52.955,73.857 53.919,72.893 v1(53.924,72.893)
  Bottom Layer w0.254: v1(53.924,72.893) 53.975,72.842 53.975,71.476 v1(54.026,71.425)
NetLD4_3: LD4.3 LD5.1 | length 12.9
  Top Layer w0.254: LD5.1 41.105,61.66 41.713,61.052 42.764,61.052 47.701,65.989 v1(47.701,66.497) ; LD4.3 47.548,68.428 v1(47.727,68.428)
  Bottom Layer w0.254: v1@47.727,66.548 v1(47.727,68.428)
NetLD5_3: LD5.3 LD6.1 | length 14.3
  Top Layer w0.254: LD6.1 38.286,54.188 40.295,54.188 40.919,54.813 40.919,59.817 41.377,60.274 v1(43.129,60.274) ; LD5.3 41.991,63.132 42.547,62.576 43.038,62.576 v1(43.104,62.509)
  Bottom Layer w0.254: v1(43.104,62.509) 43.116,62.497 43.116,60.287 v1(43.129,60.274)
NetLD6_3: LD6.3 LD7.1 | length 13.4
  Top Layer w0.254: LD7.1 39.807,46.482 40.386,47.062 v1(40.386,51.689) ; LD6.3 38.726,55.83 39.877,55.83 v1(40.081,55.626)
  Bottom Layer w0.254: v1(40.081,55.626) 40.081,55.609 40.386,55.304 v1(40.386,51.689)
NetLD7_3: LD7.3 LD8.1 | length 23.3
  Top Layer w0.254: LD7.3 39.089,48.182 39.319,48.412 39.319,52.172 39.7,52.553 40.97,52.553 41.3,52.222 41.3,39.853 40.209,38.761 38.867,38.761 LD8.1
NetLD8_3: LD8.3 LD9.1 | length 13
  Top Layer w0.254: LD8.3 38.457,40.433 40.306,40.433 v1(40.335,40.462) ; v1(41.453,38.735) 41.453,36.703 43.383,34.773 43.383,32.682 42.165,31.464 LD9.1
  Bottom Layer w0.254: v1(40.335,40.462) 41.387,39.411 41.387,38.801 v1(41.453,38.735)
NetLD9_3: LD9.3 LD10.1 | length 14
  Top Layer w0.254: LD9.3 41.315,32.936 42.418,34.039 v1(42.418,34.239) ; v1(44.196,33.249) 48.082,29.362 48.082,26.348 LD10.1
  Bottom Layer w0.254: v1(42.418,34.239) 43.205,34.239 v1(44.196,33.249)
NetLD10_3: LD10.3 LD11.1 | length 12.8
  Top Layer w0.254: LD10.3 47.067,27.737 v1(47.219,27.737) ; v1(48.844,27.686) 54.026,22.504 54.026,21.47 53.529,20.973 LD11.1
  Bottom Layer w0.254: v1(47.219,27.737) 48.768,27.737 v1@48.87,27.635
NetLD11_3: LD11.3 LD12.1 | length 13
  Top Layer w0.254: LD11.3 52.057,21.809 52.654,22.406 v1(52.654,22.784) ; v1(54.864,22.809) 56.947,20.726 60.147,20.726 61.138,19.736 61.138,18.103 LD12.1
  Bottom Layer w0.254: v1(52.654,22.784) 54.839,22.784 v1(54.864,22.809)
NetLD12_3: LD12.3 LD13.1 | length 13.4
  Top Layer w0.254: LD12.3 59.461,18.509 v1(59.461,19.888) ; v1(62.154,19.914) 68.402,19.914 68.91,19.406 LD13.1
  Bottom Layer w0.254: v1(59.461,19.888) 62.128,19.888 v1(62.154,19.914)
NetLD13_3: LD13.3 LD14.1 | length 13.3
  Top Layer w0.254: v1@67.183,18.796 v1(67.21,18.769) LD13.3 ; v1(70.104,18.796) 70.104,19.71 70.383,19.99 76.175,19.99 76.639,19.525 76.639,18.692 LD14.1
  Bottom Layer w0.254: v1(67.21,18.769) 67.237,18.796 v1(70.104,18.796)
NetLD14_3: LD14.3 LD15.1 | length 12.4
  Top Layer w0.254: v1(74.727,19.253) 74.997,18.983 74.997,18.252 LD14.3 ; v1(76.251,20.752) 79.299,20.752 81.28,22.733 83.295,22.733 83.979,22.048 LD15.1
  Bottom Layer w0.254: v1(74.727,19.253) 76.225,20.752 v1(76.251,20.752)
NetLD15_3: LD15.3 LD16.1 | length 13.6
  Top Layer w0.254: v1(81.712,23.546) 83.439,23.546 88.087,28.194 88.968,28.194 LD16.1 ; v1@81.737,22.047 82.507,21.277 LD15.3
  Bottom Layer w0.254: v1(81.712,22.047) v1(81.712,23.546)
NetLD16_3: LD16.3 LD17.1 | length 14
  Top Layer w0.254: v1(86.716,28.067) 92.786,34.138 93.919,34.138 94.48,33.577 LD17.1 ; v1(88.036,26.746) 88.036,26.722 LD16.3
  Bottom Layer w0.254: v1@86.716,28.194 v1(86.716,28.067) v1(88.036,26.746)
NetLD17_3: LD17.3 LD18.1 | length 12.9
  Top Layer w0.254: v1(92.71,32.893) 92.938,32.893 93.726,32.105 LD17.3 ; v1(92.71,34.9) 95.021,37.211 95.021,40.818 95.428,41.224 97.296,41.224 LD18.1
  Bottom Layer w0.254: v1(92.71,32.893) v1(92.71,34.9)
NetLD18_3: LD18.3 LD19.1 | length 12.5
  Top Layer w0.254: v1(95.783,39.853) 96.003,39.633 96.805,39.633 LD18.3 ; v1(95.809,42.012) 95.809,48.514 96.291,48.997 LD19.1@98.027,48.997
  Bottom Layer w0.254: v1(95.783,39.853) 95.783,42.012 v1@95.809,42.037
NetLD19_3: LD19.3 LD20.1 | length 13.4
  Top Layer w0.254: v1(95.167,47.327) 95.167,55.899 95.939,56.671 96.519,56.671 LD20.1 ; v1@96.698,47.32 v1(96.71,47.308) 96.722,47.296 LD19.3
  Bottom Layer w0.254: v1@95.148,47.346 95.186,47.308 v1(96.71,47.308)
NetLD20_3: LD20.3 LD21.1 | length 13.6
  Top Layer w0.254: LD21.1 93.048,63.986 92.462,63.4 92.432,63.4 92.253,63.221 92.253,61.316 94.526,59.042 v1(94.526,54.699) ; v1(95.809,54.686) 96.13,55.007 96.937,55.007 LD20.3
  Bottom Layer w0.254: v1@94.513,54.712 v1(94.526,54.699) 94.539,54.686 v1(95.809,54.686)
NetLD21_3: LD21.3 LD22.1 | length 13.7
  Top Layer w0.254: LD22.1 87.173,69.029 87.173,67.615 91.338,63.449 v1(91.338,61.697) ; v1@92.989,61.697 v1(93.083,61.697) 93.177,61.697 93.994,62.514 LD21.3
  Bottom Layer w0.254: v1(91.338,61.697) v1(93.083,61.697)
NetLD22_3: LD22.3 LD23.1 | length 15.1
  Top Layer w0.254: LD23.1 81.675,74.424 80.848,73.597 80.848,71.78 81.483,71.145 85.268,71.145 86.411,70.002 v1(86.411,67.742) ; v1(88.367,67.742) 88.367,67.819 LD22.3
  Bottom Layer w0.254: v1(86.411,67.742) v1(88.367,67.742)
NetLD23_3: LD23.3 LD24.1 | length 14.7
  Top Layer w0.254: LD24.1 74.059,77.063 74.059,76.607 74.041,76.588 74.041,75.692 75.209,74.524 79.553,74.524 80.01,74.066 v1(80.01,71.907) ; v1@81.712,71.73 v1(81.712,71.934) 81.712,72.139 83.147,73.574 LD23.3
  Bottom Layer w0.254: v1(80.01,71.907) 81.685,71.907 v1(81.712,71.934)
NetLD24_3: LD24.3 LD25.1 | length 111.6
  Top Layer w0.254: v1(75.565,75.286) 75.769,75.49 75.769,76.691 LD24.3 ; LD25.1 81.585,11.783 81.585,13.466 81.734,13.614 101.473,13.614 102.641,14.783 102.641,71.399 101.219,72.822 v1(99.873,72.822)
  Bottom Layer w0.254: v1(75.565,75.286) 75.565,73.101 75.844,72.822 v1(99.873,72.822)
NetLD25_3: LD25.3 LD26.1 | length 13.1
  Top Layer w0.254: LD26.1 76.505,11.764 76.505,14.326 77.241,15.062 v1(83.312,15.062) ; LD25.3 83.235,11.733 83.235,12.925 v1(83.244,12.933)
  Bottom Layer w0.254: v1(83.244,12.933) 83.278,12.967 83.278,15.028 v1(83.312,15.062)
NetLD26_3: LD26.3 LD27.1 | length 10.5
  Top Layer w0.254: LD27.1 71.562,13.244 71.787,13.468 71.858,13.54 72.98,13.564 73.312,13.564 73.564,13.568 v1(75.819,13.614) ; LD26.3 v1(78.245,13.652) v1@78.257,13.665
  Bottom Layer w0.254: v1(75.819,13.614) 76.149,13.945 77.923,13.945 78.215,13.652 v1(78.245,13.652)
NetLD27_3: LD27.3 LD28.1 | length 11.4
  Top Layer w0.254: LD28.1 66.58,13.621 67.031,14.072 73.101,14.072 v1(73.279,14.249) ; LD27.3 v1(73.262,12.883)
  Bottom Layer w0.254: v1(73.262,12.883) 73.271,12.891 73.271,14.241 v1(73.279,14.249)
NetLD28_3: LD28.3 LD29.1 | length 10
  Top Layer w0.254: LD29.1 61.62,11.747 61.62,12.954 62.408,13.741 64.6,13.741 64.803,13.538 v1(64.897,13.538) ; LD28.3 68.28,13.238 v1(68.303,13.261) v1@68.326,13.284
  Bottom Layer w0.254: v1(64.897,13.538) 67.932,13.538 68.209,13.261 v1(68.303,13.261)
NetLD29_3: LD29.3 LD30.1 | length 10.2
  Top Layer w0.254: LD30.1 56.615,13.593 56.764,13.741 60.757,13.741 v1(61.087,13.411) ; LD29.3 v1(63.298,12.904) v1@63.322,12.929
  Bottom Layer w0.254: v1(61.087,13.411) 61.168,13.411 61.675,12.904 v1(63.298,12.904)
NetLD30_3: LD30.3 LD31.1 | length 9.7
  Top Layer w0.254: LD31.1 51.613,11.745 51.613,13.183 51.892,13.462 v1(55.855,13.462) ; LD30.3 v1(58.315,12.925) v1@58.318,12.929
  Bottom Layer w0.254: v1(55.855,13.462) 55.88,13.487 57.753,13.487 v1(58.315,12.925)
NetLED1_1: LED1.1 R7.1 | length 3.4
  Bottom Layer w0.254: R7.1 12.548,32.309 12.751,32.106 12.751,29.948 LED1.1
NetQ1_1: 
NetQ1_3: 
NetR1_2: R1.2 | length 46.4
  Bottom Layer w0.254: R1.2 44.12,49.733 45.161,50.775 45.161,59.334 53.288,67.461 67.26,67.461 67.488,67.234 67.488,64.17
NetR2_2: R2.2 | length 13.9
  Bottom Layer w0.254: R2.2@36.743,48.26 R2.2 48.108,48.184 48.285,48.362 48.539,48.362 ; 49.936,47.447 50.063,47.32 50.243,47.32 50.475,47.552 51.318,47.552 51.561,47.795
NetR3_2: R3.2 | length 20.1
  Bottom Layer w0.254: R3.2 44.044,46.609 44.831,45.822 44.831,40.081 46.152,38.76 50.267,38.76
NetR4_2: R4.2 | length 61.4
  Bottom Layer w0.254: R4.2 43.078,45.009 43.459,44.628 43.459,37.77 57.099,24.13 76.149,24.13 77.546,25.527 77.546,31.039 ; 77.724,30.861 79.09,32.227
NetR6_2: R6.2 USB_POWER.A5 | length 2.7
  Bottom Layer w0.254: USB_POWER.A5 7.851,22.665 R6.2
NetR8_2: R8.2 USB_POWER.B5 | length 2.6
  Bottom Layer w0.254: USB_POWER.B5 8.308,23.665 R8.2
NetR10_2: R10.2 | length 51.4
  Bottom Layer w0.254: R10.2 21.031,36.713 21.031,22.53 22.25,21.311 36.627,21.311 48.158,9.779 51.384,9.779 52.4,8.763
NetR11_2: R11.2 | length 53.7
  Bottom Layer w0.254: R11.2 25.959,36.713 25.959,24.638 26.899,23.698 37.541,23.698 50.368,10.871 58.699,10.871 59.614,9.957 59.614,8.966 60.223,8.357
NetR13_2: R13.2 | length 63.9
  Bottom Layer w0.254: R13.2 27.534,36.713 27.534,27.102 28.423,26.213 38.887,26.213 50.317,14.783 69.596,14.783 70.587,13.792 70.587,8.611 70.917,8.28
NetR14_2: R14.2 | length 70.6
  Bottom Layer w0.254: R14.2 29.972,36.713 29.972,29.794 31.166,28.6 40.589,28.6 51.714,17.475 78.257,17.475 80.467,15.265 80.467,9.677 80.467,8.814 80.899,8.382
NetR15_2: K1.Touch R15.2 | length 24.8
  Bottom Layer w0.254: K1.Touch 14.326,14.412 14.326,36.713 R15.2
NetR16_2: K2.Touch R16.2 | length 35.1
  Bottom Layer w0.254: R16.2 16.358,36.713 16.358,21.666 24.536,13.487 31.879,13.487 K2.Touch
NetR17_1: R17.1 SMG.12 | length 48.4
  Bottom Layer w0.254: SMG.12 13.65,75.474 14.122,75.946 34.392,75.946 35.23,75.108 35.23,57.252 34.62,56.642 R17.1
NetR18_1: R18.1 SMG.9 | length 35.3
  Bottom Layer w0.254: SMG.9 21.27,74.813 21.895,75.438 33.096,75.438 33.579,74.955 33.579,58.496 33.172,58.09 R18.1
NetR19_1: R19.1 SMG.8 | length 27.4
  Bottom Layer w0.254: SMG.8 23.81,74.559 24.105,74.854 31.921,74.854 32.106,74.669 32.106,60.223 31.42,59.538 R19.1
NetU2_6: U2.6 X1.1 | length 3.8
  Bottom Layer w0.254: X1.1 5.814,56.122 6.645,55.291 U2.6
NRST: C4.2 DEBUG1.5 R20.1 RST.2 U1.6 | length 49.4
  Top Layer w0.254: v1(5.639,51.206) 5.639,49.962 6.147,49.454 11.811,49.454 12.09,49.174 DEBUG1.5
  Bottom Layer w0.254: RST.2 2.032,63.576 1.473,63.017 1.473,51.892 2.159,51.206 v1(5.639,51.206) ; DEBUG1.5 12.482,47.828 12.895,47.415 12.91,47.415 13.462,46.863 22.86,46.863 24.79,44.933 U1.6 24.79,40.157 24.221,39.588 R20.1 24.247,38.379 C4.2
RF_IO: R9.1 U1.12 U2.4 | length 21
  Top Layer w0.254: v1(17.17,44.221) 17.17,47.531 v1(17.183,47.544)
  Bottom Layer w0.254: U2.4 10.351,55.016 R9.1 10.363,54.902 11.074,54.191 11.074,49.784 11.532,49.327 16.612,49.327 17.183,48.755 v1(17.183,47.544) ; v1@17.145,44.247 v1(17.17,44.221) U1.12
SEGA: SMG.11 U1.17 | length 22.4
  Bottom Layer w0.254: SMG.11 17.421,72.073 17.421,61.947 17.17,61.697 U1.17
SEGB: SMG.7 U1.21 | length 23.5
  Bottom Layer w0.254: U1.21 22.25,58.42 25.041,61.211 25.041,71.995 SMG.7
SEGC: SMG.4 U1.19 | length 12.3
  Bottom Layer w0.254: U1.19 19.71,59.792 21.27,61.351 SMG.4
SEGD: SMG.2 U1.16 | length 11.8
  Bottom Layer w0.254: U1.16 15.9,62.464 16.19,62.753 SMG.2
SEGE: SMG.1 U1.15 | length 12
  Bottom Layer w0.254: SMG.1 14.63,62.164 U1.15
SEGF: SMG.10 U1.18 | length 22.9
  Bottom Layer w0.254: U1.18 18.44,60.782 19.961,62.303 19.961,72.073 SMG.10
SEGG: SMG.5 U1.20 | length 12.8
  Bottom Layer w0.254: U1.20 20.98,59.075 23.81,61.905 SMG.5
SWCLK: DEBUG1.4 U1.7 | length 18.9
  Bottom Layer w0.254: DEBUG1.4 9.811,47.567 9.811,46.856 10.312,46.355 22.301,46.355 23.52,45.136 U1.7
SWDIO: DEBUG1.2 U1.8 | length 22.8
  Bottom Layer w0.254: DEBUG1.2 4.47,46.152 4.775,45.847 20.752,45.847 22.25,44.348 U1.8
TK1: R1.1 U1.28 | length 5.5
  Bottom Layer w0.254: U1.28 31.14,50.089 31.496,49.733 R1.1
TK2: R3.1 U1.26 | length 11
  Bottom Layer w0.254: U1.26 28.6,47.371 29.362,46.609 R3.1
TK3: R10.1 U1.9 | length 3.4
  Bottom Layer w0.254: R10.1@20.904,38.394 R10.1 20.98,38.369 U1.9
TK4: R13.1 U1.4 | length 3.5
  Bottom Layer w0.254: U1.4 27.33,38.471 R13.1
TK5: R2.1 U1.27 | length 8.3
  Bottom Layer w0.254: U1.27 29.87,48.641 30.328,48.184 R2.1
TK6: R4.1 U1.22 | length 15.3
  Bottom Layer w0.254: U1.22 23.52,50.013 28.524,45.009 R4.1
TK7: R11.1 U1.5 | length 3.5
  Bottom Layer w0.254: R11.1 26.06,38.471 U1.5
TK8: R14.1 U1.2 | length 3.4
  Bottom Layer w0.254: U1.2 29.87,38.369 R14.1
TK9: R15.1 U1.14 | length 3.5
  Bottom Layer w0.254: R15.1 14.63,38.674 U1.14
TK10: R16.1 U1.13 | length 3.6
  Bottom Layer w0.254: U1.13 15.9,38.725 R16.1
V5V: 5V.1 C1.2 E1.1 F1.2 LD1.2 LD2.2 LD3.2 LD4.2 LD5.2 LD6.2 LD7.2 LD8.2 LD9.2 LD10.2 LD11.2 LD12.2 LD13.2 LD14.2 LD15.2 LD16.2 LD17.2 LD18.2 LD19.2 LD20.2 LD21.2 LD22.2 LD23.2 LD24.2 LD25.2 LD26.2 LD27.2 LD28.2 LD29.2 LD30.2 LD31.2 V1.3 | length 347.7
  Top Layer w0.381: LD31.2 52.483,10.715 52.632,10.566 57.571,10.566 ; LD30.2 57.465,10.672 57.571,10.566 ; LD29.2 62.448,10.628 62.509,10.566 ; LD28.2 67.43,10.585 67.412,10.566 ; LD27.2 72.412,10.589 72.39,10.566 ; LD26.2 77.395,10.591 77.419,10.566 ; LD25.2 82.377,10.715 82.228,10.566 ; 84.532,19.176 86.106,17.602 v1(86.106,14.961) ; v1(86.106,12.933) 86.106,10.795 85.877,10.566 82.377,10.566 82.228,10.566 ; 57.571,10.566 62.509,10.566 ; 62.509,10.566 67.412,10.566 ; 67.412,10.566 72.39,10.566 ; 72.39,10.566 77.419,10.566 ; 77.419,10.566 82.228,10.566
  Top Layer w0.508: v2(4.699,32.944) 4.88,32.944 5.617,32.207 38.47,32.207 38.645,32.032 ; LD7.2 34.915,47.295 ; LD6.2 36.032,55.709 ; LD8.2 36.035,38.724 ; LD5.2 39.526,63.422 39.524,63.423 ccw(c39.276,62.98) 39.519,63.426 39.274,63.559 ; LD9.2 39.311,30.819 ; LD4.2 44.42,70.311 ; LD10.2 44.547,24.014 44.538,24.014 ; LD3.2 51.006,75.445 ; LD11.2 51.296,18.829 ; 59.338,15.512 cw(c67.713,47.222) 51.296,18.829 ; LD2.2 58.78,78.778 ; LD12.2 59.36,15.596 59.563,15.392 67.716,15.392 68.06,15.736 LD13.2 ; LD1.2 67.156,80.009 ; LD24.2 75.644,79.032 ; LD14.2 76.953,15.851 77.247,15.939 ccw(c67.69,47.263) 79.431,16.691 82.235,17.921 ccw(c67.69,47.263) 83.867,18.788 ; LD23.2 83.246,75.578 cw(c83.687,75.325) 83.425,75.76 83.542,75.831 ; 83.216,18.42 83.22,18.423 ; LD15.2 84.532,19.176 ; 83.863,18.795 83.867,18.788 ; 83.871,18.782 83.867,18.788 ; LD22.2 89.817,70.472 ; LD16.2 91.382,24.653 ; LD21.2 95.327,64.222 cw(c95.588,63.786) 95.377,64.248 95.623,64.36 ; LD17.2 95.734,31.922 ; 96.029,63.67 96.032,63.672 ; LD20.2 99.09,56.569 ; LD18.2 98.784,39.856 ; LD19.2 99.552,48.158 ; 99.309,55.776 99.313,55.777 ; 34.915,47.295 ccw(c67.713,47.222) 35.809,39.617 ccw(c67.713,47.222) 36.035,38.724 ; 34.915,47.295 cw(c67.713,47.222) 34.929,48.165 cw(c67.713,47.222) 36.032,55.709 ; 36.032,55.709 cw(c67.713,47.222) 36.265,56.532 cw(c67.713,47.222) 39.274,63.559 ; 36.035,38.724 ccw(c67.713,47.222) 38.645,32.032 ; 38.645,32.032 ccw(c67.713,47.222) 39.311,30.819 ; 39.274,63.559 cw(c67.713,47.222) 39.726,64.322 cw(c67.713,47.222) 44.42,70.311 ; 39.311,30.819 ccw(c67.713,47.222) 39.607,30.317 ccw(c67.713,47.222) 43.957,24.609 ccw(c67.713,47.222) 44.538,24.014 ; 44.42,70.311 cw(c67.713,47.222) 45.039,70.92 cw(c67.713,47.222) 51.006,75.445 ; 44.538,24.014 ccw(c67.713,47.222) 50.646,19.215 ccw(c67.713,47.222) 51.296,18.829 ; 51.006,75.445 cw(c67.713,47.222) 51.807,75.904 cw(c67.69,47.263) 58.78,78.778 ; 58.78,78.778 cw(c67.69,47.263) 59.653,79.012 cw(c67.69,47.263) 67.156,80.009 ; 67.156,80.009 cw(c67.69,47.263) 73.953,79.409 74.54,79.294 75.117,79.16 cw(c67.69,47.263) 75.644,79.032 ; 75.644,79.032 cw(c67.69,47.263) 76.415,78.829 cw(c67.69,47.263) 81.61,76.907 82.442,76.517 83.237,76.087 83.542,75.831 ; 83.542,75.831 87.552,72.457 89.465,70.824 89.817,70.472 ; 83.867,18.788 ccw(c67.69,47.263) 84.532,19.176 ; 84.532,19.176 ccw(c67.69,47.263) 84.814,19.348 89.942,23.234 ccw(c67.69,47.263) 90.736,23.995 ccw(c67.69,47.263) 91.382,24.653 ; 89.817,70.472 90.169,70.12 95.465,64.615 cw(c67.69,47.263) 95.623,64.36 ; 91.382,24.653 ccw(c67.69,47.263) 91.505,24.782 95.734,31.922 ; 95.623,64.36 cw(c67.69,47.263) 96.032,63.672 ; 95.734,31.922 97.272,34.52 98.784,39.856 ; 96.032,63.672 cw(c67.69,47.263) 96.568,62.71 99.01,56.835 cw(c67.69,47.263) 99.09,56.569 ; 98.784,39.856 99.525,42.474 99.552,48.158 ; 99.09,56.569 cw(c67.69,47.263) 99.313,55.777 ; 99.313,55.777 cw(c67.69,47.263) 99.582,54.71 99.552,48.158
  Bottom Layer w0.381: v1(86.106,12.933) v1(86.106,14.961)
  Bottom Layer w0.6: V1.3 1.999,37.103 1.999,35.72 2.689,35.03 2.689,30.331 F1.2 ; C1.2 2.788,34.133 3.586,34.133 5.41,32.309 5V.1
VBUS: F1.1 USB_POWER.A9 USB_POWER.B9 | length 17.4
  Bottom Layer w0.6: F1.1 7.163,30.302 7.976,29.489 7.976,25.4 7.36,24.785 5.931,24.785 USB_POWER.A9 3.704,24.685 3.353,24.333 3.353,22.047 3.755,21.645 USB_POWER.B9
VCC: C3.2 C5.2 C6.2 DEBUG1.1 JUMP.2 R5.1 R20.2 U1.1 U2.5 | length 65.5
  Top Layer w0.4: v1(7.597,50.343) 11.71,50.343 12.141,50.775 v1(12.141,56.617) ; JUMP.2 11.119,39.377 22.64,39.377 22.646,39.37 v1@31.598,39.37
  Bottom Layer w0.4: U2.5 7.588,55.01 7.588,51.264 C6.2 7.582,50.33 7.214,49.962 2.616,49.962 1.93,49.276 DEBUG1.1 1.93,41.224 2.642,40.513 JUMP.2 ; R5.1 12.116,57.747 12.116,56.642 v1(12.141,56.617) ; v1(22.646,39.383) 22.657,39.373 22.657,38.415 R20.2 ; U1.1 31.19,41.659 31.19,40.92 31.557,40.553 C3.2
  other v1: 31.612,39.383
pads on no net: LD31.3 SMG.3 SMG.6 U1.10 USB_POWER.0 V1.2@4.242,43.637

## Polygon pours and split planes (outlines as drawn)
GND on Bottom Layer "GND_L02_P001" (hatched 45Degree grid 0.762 track 0.203, remove dead copper, pour order 1): -0.279,80.899 -0.203,80.823 -0.203,-0.102 105.004,-0.102 105.08,-0.025 105.08,80.899
GND on Top Layer "GND_L01_P000" (hatched 45Degree grid 0.762 track 0.203, remove dead copper, pour order 0): -0.229,80.924 -0.152,80.848 -0.152,-0.076 105.054,-0.076 105.131,0 105.131,80.924

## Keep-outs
Keep-Out Layer:
  lines w0.025: -0.076,-0.051 104.978,-0.051 104.978,80.772 -0.076,80.772 -0.076,-0.051

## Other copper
Top Layer:
  pour cut-out: 35.526,19.005 ccw(c32.698,11.91) 25.603,14.738 ccw(c32.477,12.424)
  pour cut-out: 15.613,19.386 ccw(c12.784,12.291) 5.689,15.119 ccw(c12.563,12.805)
  pour cut-out: 51.854,9.538 ccw(c51.644,8.516) 50.622,8.725 50.622,1.905 ccw(c51.854,1.905) 51.854,0.673 83.985,0.673 ccw(c84.106,2.026) 85.458,1.904 85.458,8.318 ccw(c84.105,8.183) 83.985,9.538
  pour cut-out: 67.79,69.262 ccw(c67.869,46.908) 45.529,47.686 ccw(c67.124,47.658) 68.43,26.102 ccw(c67.831,48.016) 89.749,47.644 ccw(c68.348,47.867)
  pour cut-out: 9.709,58.972 7.576,58.972 7.576,70.021 6.356,70.021 6.356,80.715 57.156,80.715 57.156,76.854 11.462,76.854 11.462,58.947
Bottom Layer:
  pour cut-out: 51.854,9.538 ccw(c51.644,8.516) 50.622,8.725 50.622,1.905 ccw(c51.854,1.905) 51.854,0.673 83.985,0.673 ccw(c84.106,2.026) 85.458,1.904 85.458,8.318 ccw(c84.105,8.183) 83.985,9.538
  pour cut-out: 67.942,69.109 ccw(c68.021,46.756) 45.681,47.534 ccw(c67.277,47.506) 68.582,25.95 ccw(c67.983,47.863) 89.902,47.491 ccw(c68.501,47.714)
  pour cut-out: 9.703,58.979 7.569,58.979 7.569,70.028 6.35,70.028 6.35,80.721 57.15,80.721 57.15,76.86 11.455,76.86 11.455,58.953

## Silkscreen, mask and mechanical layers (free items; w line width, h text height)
Top Overlay:
  drawing of 448 lines, arcs and shapes, not listed
  text "SWCLK" at 8.887,46.304 h1 r270
  text "SWDIO" at 4.076,46.101 h1 r270
  text "GND" at 6.474,45.542 h1 r270
  text "VCC" at 1.394,45.415 h1 r270
  text "RST" at 11.493,45.288 h1 r270
  text "WWW.PUYASEMI.COM" at 8.28,34.265 h1.57
  text "PY32T020 Touch Demo-2 V2.0" at 2.286,31.979 h1.57
  text "202407" at 14.935,28.981 h1.57

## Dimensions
-0.076,-0.051 to 104.978,-0.051 on Top Overlay
-0.076,80.772 to -0.076,-0.051 on Top Overlay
